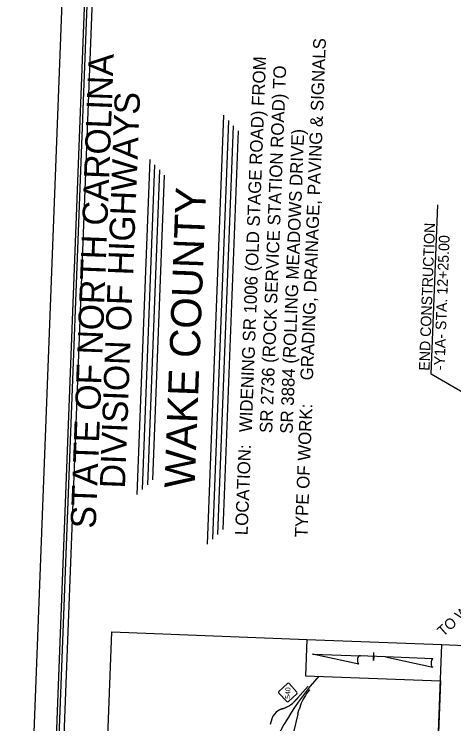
# Model space of a CAD drawing. Extents: x 2094564 to 2100382, y 679033 to 692366.
# Drawn here: x 2094564 to 2096747, y 684877 to 688399 of the extents above; entities that cross this region are included whole.
import ezdxf

# ---------------------------------------------------------------- set-up
doc = ezdxf.new("R2010")
doc.units = 0
for name, color, linetype in [('Old_Level_1', 7, 'Continuous'), ('Pattern 17', 7, 'Continuous'), ('Prop Horizontal Alignment Direction Label', 7, 'Continuous'), ('Prop Horizontal Alignment Station Label', 7, 'Continuous'), ('Prop Horizontal Alignment Tick Label', 7, 'Continuous'), ('Prop Horizontal Alignment Tick Large', 7, 'Continuous'), ('Scratch_Level_0', 7, 'Continuous')]:
    doc.layers.add(name, color=color, linetype=linetype)

msp = doc.modelspace()

# ---------------------------------------------------------------- linework, layer by layer
at = {"layer": 'Old_Level_1'}
for p, q in [((2096044.5, 685222.5), (2096044.5, 685222.3)), ((2096044.5, 685222.5), (2096044.5, 685222.3)), ((2096044.5, 685222.5), (2096283.3, 685213.4)), ((2096274.5, 685172.4), (2096044.5, 685222.3)), ((2096348.5, 685191.1), (2096350, 685231.1)), ((2096407.2, 685208.6), (2096276.3, 685213.7)), ((2096283.3, 685213.4), (2096276.6, 685213.6)), ((2096349.2, 685208.6), (2096348.5, 685190.9)), ((2096348.5, 685190.9), (2096348.5, 685190.6)), ((2096407.2, 685208.6), (2096641.7, 685157.9)), ((2096642.3, 685199.9), (2096407.2, 685208.6))]:
    msp.add_line(p, q, dxfattribs=at)
for centre, start_param, end_param in [((2096277.7, 685193), 0.216388, 2.908219), ((2096643.3, 685179), 0.201328, 3.141593)]:
    msp.add_ellipse(centre, major_axis=(1, 21.1), ratio=0.461098, start_param=start_param, end_param=end_param, dxfattribs=at)
at = {"layer": 'Pattern 17'}
for p, q in [((2096016.8, 685295.7), (2096687.2, 685270)), ((2095878.4, 685037.6), (2095920.5, 685076.5)), ((2095928.6, 685076.2), (2095967.6, 685034.2)), ((2095917, 684987.4), (2095878.1, 685029.4)), ((2095967.3, 685026), (2095925.2, 684987.1))]:
    msp.add_line(p, q, dxfattribs=at)
for points in [[(2094975.9, 683430.3), (2095048.9, 685332.8), (2096016.8, 685295.7), (2096009.9, 685115.7), (2096680.3, 685090), (2096614.3, 683367.4)], [(2096614.3, 683367.4), (2096687.2, 685270), (2096881.4, 685262.6), (2096808.4, 683360)]]:
    msp.add_lwpolyline(points, close=True, dxfattribs=at)
for centre, start, end in [((2095924.4, 685072.3), 42.8037, 132.8037), ((2095882.3, 685033.4), 132.8037, 222.8037), ((2095963.3, 685030.3), 312.8037, 42.8037), ((2095921.3, 684991.3), 222.8037, 312.8037)]:
    msp.add_arc(centre, 5.78, start, end, dxfattribs=at)
at = {"layer": 'Prop Horizontal Alignment Direction Label'}
for p, q in [((2095523.6, 685768.8), (2095605.3, 687897.3)), ((2095549.5, 685792.8), (2095629.3, 687871.3)), ((2095575.5, 685816.9), (2095653.3, 687845.4)), ((2095601.4, 685840.9), (2095677.4, 687819.4)), ((2095174.9, 686015.6), (2095238.6, 687678.1)), ((2095200.7, 686039.6), (2095262.6, 687652.2)), ((2095226.7, 686063.7), (2095286.6, 687626.3)), ((2095252.7, 686087.7), (2095310.6, 687600.3)), ((2096023.6, 685063.4), (2095970.3, 685003.4)), ((2095843.3, 684901.7), (2095834.1, 684873.9)), ((2095972.4, 684924.8), (2095951.4, 684835.4))]:
    msp.add_line(p, q, dxfattribs=at)
for points in [[(2095006.3, 690563.5), (2094722.6, 683168.8)], [(2095030.3, 690537.5), (2094758.2, 683442.8)]]:
    msp.add_lwpolyline(points, dxfattribs=at)
for centre, radius, start, end in [((2097122.1, 684172.2), 1406.2, 138.0034, 159.4705), ((2096223.9, 684878), 255.5, 144.4694, 164.2013), ((2095856.4, 685087.2), 140.6, 296.8602, 313.1346), ((2095913.2, 684878.8), 73.6, 120.2754, 161.8296)]:
    msp.add_arc(centre, radius, start, end, dxfattribs=at)
for points in [[(2096030.2, 685045.1), (2096030, 685044.8), (2096029.8, 685044.6), (2096029.6, 685044.3), (2096029.4, 685044.1), (2096029.2, 685043.8), (2096029, 685043.6), (2096028.8, 685043.3), (2096028.6, 685043.1), (2096028.4, 685042.8), (2096028.2, 685042.6), (2096028, 685042.3), (2096027.8, 685042.1), (2096027.6, 685041.8), (2096027.4, 685041.6), (2096027.2, 685041.3), (2096027.1, 685041.1), (2096026.9, 685040.8), (2096026.7, 685040.6), (2096026.5, 685040.3), (2096026.3, 685040.1), (2096026.1, 685039.8), (2096025.9, 685039.6), (2096025.7, 685039.3), (2096025.5, 685039.1), (2096025.3, 685038.8), (2096025.1, 685038.6), (2096024.9, 685038.3), (2096024.7, 685038.1), (2096024.5, 685037.9), (2096024.3, 685037.6), (2096024.1, 685037.4), (2096023.9, 685037.1), (2096023.7, 685036.9), (2096023.5, 685036.6), (2096023.3, 685036.3), (2096023.1, 685036.1), (2096023, 685035.8), (2096022.8, 685035.6), (2096022.6, 685035.3), (2096022.4, 685035.1), (2096022.2, 685034.8), (2096022, 685034.6), (2096021.8, 685034.3), (2096021.6, 685034.1), (2096021.4, 685033.8), (2096021.2, 685033.6), (2096021, 685033.3), (2096020.8, 685033.1), (2096020.7, 685032.8), (2096020.5, 685032.6), (2096020.3, 685032.3), (2096020.1, 685032.1), (2096019.9, 685031.8), (2096019.7, 685031.6), (2096019.5, 685031.3), (2096019.3, 685031.1), (2096019.1, 685030.8), (2096018.9, 685030.5), (2096018.8, 685030.3), (2096018.6, 685030), (2096018.4, 685029.8), (2096018.2, 685029.5), (2096018, 685029.3), (2096017.8, 685029), (2096017.6, 685028.8), (2096017.4, 685028.5), (2096017.3, 685028.2), (2096017.1, 685028), (2096016.9, 685027.7), (2096016.7, 685027.5), (2096016.5, 685027.2), (2096016.3, 685027), (2096016.1, 685026.7), (2096016, 685026.4)], [(2095970.3, 685003.4), (2095970, 685003.1), (2095969.8, 685002.8), (2095969.6, 685002.6), (2095969.4, 685002.3), (2095969.1, 685002.1), (2095968.9, 685001.8), (2095968.7, 685001.5), (2095968.4, 685001.3), (2095968.2, 685001), (2095968, 685000.8), (2095967.7, 685000.5), (2095967.5, 685000.2), (2095967.3, 685000), (2095967, 684999.7), (2095966.8, 684999.5), (2095966.6, 684999.2), (2095966.3, 684998.9), (2095966.1, 684998.7), (2095965.9, 684998.4), (2095965.6, 684998.2), (2095965.4, 684997.9), (2095965.2, 684997.6), (2095964.9, 684997.4), (2095964.7, 684997.1), (2095964.5, 684996.9), (2095964.2, 684996.6), (2095964, 684996.3), (2095963.8, 684996.1), (2095963.5, 684995.8), (2095963.3, 684995.6), (2095963.1, 684995.3), (2095962.8, 684995.1), (2095962.6, 684994.8), (2095962.4, 684994.5), (2095962.1, 684994.3), (2095961.9, 684994), (2095961.6, 684993.8), (2095961.4, 684993.5), (2095961.2, 684993.3), (2095960.9, 684993), (2095960.7, 684992.8), (2095960.5, 684992.5), (2095960.2, 684992.3), (2095960, 684992), (2095959.7, 684991.8), (2095959.5, 684991.5), (2095959.3, 684991.2), (2095959, 684991), (2095958.8, 684990.7), (2095958.5, 684990.5), (2095958.3, 684990.2), (2095958, 684990), (2095957.8, 684989.7), (2095957.6, 684989.5), (2095957.3, 684989.2), (2095957.1, 684989), (2095956.8, 684988.8), (2095956.6, 684988.5), (2095956.3, 684988.3), (2095956.1, 684988), (2095955.8, 684987.8), (2095955.6, 684987.5), (2095955.3, 684987.3), (2095955.1, 684987), (2095954.8, 684986.8), (2095954.6, 684986.5), (2095954.3, 684986.3), (2095954.1, 684986.1), (2095953.8, 684985.8), (2095953.6, 684985.6), (2095953.3, 684985.3), (2095953.1, 684985.1), (2095952.8, 684984.9), (2095952.6, 684984.6)], [(2095896.3, 684951.6), (2095896, 684951.5), (2095895.8, 684951.3), (2095895.5, 684951.2), (2095895.2, 684951.1), (2095894.9, 684951), (2095894.6, 684950.9), (2095894.4, 684950.8), (2095894.1, 684950.7), (2095893.8, 684950.6), (2095893.5, 684950.5), (2095893.2, 684950.3), (2095893, 684950.2), (2095892.7, 684950.1), (2095892.4, 684950), (2095892.1, 684949.9), (2095891.8, 684949.8), (2095891.6, 684949.7), (2095891.3, 684949.6), (2095891, 684949.4), (2095890.7, 684949.3), (2095890.4, 684949.2), (2095890.2, 684949.1), (2095889.9, 684949), (2095889.6, 684948.9), (2095889.3, 684948.8), (2095889.1, 684948.6), (2095888.8, 684948.5), (2095888.5, 684948.4), (2095888.2, 684948.3), (2095887.9, 684948.2), (2095887.7, 684948.1), (2095887.4, 684947.9), (2095887.1, 684947.8), (2095886.8, 684947.7), (2095886.6, 684947.6), (2095886.3, 684947.5), (2095886, 684947.3), (2095885.7, 684947.2), (2095885.5, 684947.1), (2095885.2, 684947), (2095884.9, 684946.8), (2095884.6, 684946.7), (2095884.4, 684946.6), (2095884.1, 684946.5), (2095883.8, 684946.3), (2095883.5, 684946.2), (2095883.3, 684946.1), (2095883, 684946), (2095882.7, 684945.8), (2095882.5, 684945.7), (2095882.2, 684945.6), (2095881.9, 684945.4), (2095881.6, 684945.3), (2095881.4, 684945.2), (2095881.1, 684945), (2095880.8, 684944.9), (2095880.6, 684944.8), (2095880.3, 684944.6), (2095880, 684944.5), (2095879.8, 684944.4), (2095879.5, 684944.2), (2095879.2, 684944.1), (2095879, 684944), (2095878.7, 684943.8), (2095878.4, 684943.7), (2095878.2, 684943.5), (2095877.9, 684943.4), (2095877.6, 684943.2), (2095877.4, 684943.1), (2095877.1, 684942.9), (2095876.9, 684942.8), (2095876.6, 684942.6), (2095876.3, 684942.5), (2095876.1, 684942.3)], [(2095896.3, 684951.6), (2095896.6, 684951.7), (2095897, 684951.8), (2095897.3, 684952), (2095897.6, 684952.1), (2095897.9, 684952.2), (2095898.3, 684952.3), (2095898.6, 684952.5), (2095898.9, 684952.6), (2095899.2, 684952.7), (2095899.6, 684952.9), (2095899.9, 684953), (2095900.2, 684953.1), (2095900.5, 684953.2), (2095900.8, 684953.4), (2095901.2, 684953.5), (2095901.5, 684953.6), (2095901.8, 684953.8), (2095902.1, 684953.9), (2095902.5, 684954), (2095902.8, 684954.1), (2095903.1, 684954.3), (2095903.4, 684954.4), (2095903.8, 684954.5), (2095904.1, 684954.7), (2095904.4, 684954.8), (2095904.7, 684954.9), (2095905, 684955.1), (2095905.4, 684955.2), (2095905.7, 684955.3), (2095906, 684955.5), (2095906.3, 684955.6), (2095906.7, 684955.7), (2095907, 684955.9), (2095907.3, 684956), (2095907.6, 684956.1), (2095907.9, 684956.3), (2095908.3, 684956.4), (2095908.6, 684956.5), (2095908.9, 684956.7), (2095909.2, 684956.8), (2095909.5, 684957), (2095909.9, 684957.1), (2095910.2, 684957.2), (2095910.5, 684957.4), (2095910.8, 684957.5), (2095911.1, 684957.6), (2095911.5, 684957.8), (2095911.8, 684957.9), (2095912.1, 684958.1), (2095912.4, 684958.2), (2095912.7, 684958.3), (2095913.1, 684958.5), (2095913.4, 684958.6), (2095913.7, 684958.8), (2095914, 684958.9), (2095914.3, 684959.1), (2095914.6, 684959.2), (2095915, 684959.4), (2095915.3, 684959.5), (2095915.6, 684959.7), (2095915.9, 684959.8), (2095916.2, 684959.9), (2095916.5, 684960.1), (2095916.8, 684960.2), (2095917.2, 684960.4), (2095917.5, 684960.6), (2095917.8, 684960.7), (2095918.1, 684960.9), (2095918.4, 684961), (2095918.7, 684961.2), (2095919, 684961.3), (2095919.4, 684961.5), (2095919.7, 684961.6), (2095920, 684961.8)], [(2095972.4, 684924.8), (2095972.4, 684925.1), (2095972.5, 684925.4), (2095972.6, 684925.7), (2095972.6, 684926), (2095972.7, 684926.3), (2095972.8, 684926.7), (2095972.9, 684927), (2095972.9, 684927.3), (2095973, 684927.6), (2095973.1, 684927.9), (2095973.1, 684928.2), (2095973.2, 684928.5), (2095973.3, 684928.8), (2095973.4, 684929.1), (2095973.4, 684929.4), (2095973.5, 684929.7), (2095973.6, 684930), (2095973.7, 684930.4), (2095973.7, 684930.7), (2095973.8, 684931), (2095973.9, 684931.3), (2095974, 684931.6), (2095974, 684931.9), (2095974.1, 684932.2), (2095974.2, 684932.5), (2095974.2, 684932.8), (2095974.3, 684933.1), (2095974.4, 684933.4), (2095974.5, 684933.7), (2095974.5, 684934.1), (2095974.6, 684934.4), (2095974.7, 684934.7), (2095974.8, 684935), (2095974.8, 684935.3), (2095974.9, 684935.6), (2095975, 684935.9), (2095975.1, 684936.2), (2095975.1, 684936.5), (2095975.2, 684936.8), (2095975.3, 684937.1), (2095975.4, 684937.4), (2095975.4, 684937.7), (2095975.5, 684938), (2095975.6, 684938.4), (2095975.7, 684938.7), (2095975.8, 684939), (2095975.8, 684939.3), (2095975.9, 684939.6), (2095976, 684939.9), (2095976.1, 684940.2), (2095976.1, 684940.5), (2095976.2, 684940.8), (2095976.3, 684941.1), (2095976.4, 684941.4), (2095976.5, 684941.7), (2095976.5, 684942), (2095976.6, 684942.3), (2095976.7, 684942.7), (2095976.8, 684943), (2095976.9, 684943.3), (2095977, 684943.6), (2095977, 684943.9), (2095977.1, 684944.2), (2095977.2, 684944.5), (2095977.3, 684944.8), (2095977.4, 684945.1), (2095977.4, 684945.4), (2095977.5, 684945.7), (2095977.6, 684946), (2095977.7, 684946.3), (2095977.8, 684946.6), (2095977.9, 684946.9), (2095978, 684947.2), (2095978, 684947.5)]]:
    msp.add_spline(points, degree=3, dxfattribs=at)
at = {"layer": 'Prop Horizontal Alignment Station Label'}
msp.add_line((2095490.3, 686843.6), (2095490.3, 686843.6), dxfattribs=at)
at = {"layer": 'Prop Horizontal Alignment Tick Label'}
msp.add_lwpolyline([(2099950.1, 682147.8), (2100269.5, 690474.2), (2094997.8, 690676.3), (2094678.5, 682349.9)], close=True, dxfattribs=at)
at = {"layer": 'Prop Horizontal Alignment Tick Large'}
msp.add_lwpolyline([(2094886.5, 690703.1), (2094563.9, 682289.3), (2100059.8, 682078.5), (2100382.4, 690492.3)], close=True, dxfattribs=at)
at = {"layer": 'Scratch_Level_0'}
for p, q in [((2096634.8, 686612.2), (2096667, 687452.3)), ((2097643.4, 686021.5), (2096634.8, 686612.2))]:
    msp.add_line(p, q, dxfattribs=at)

# ---------------------------------------------------------------- texts
at = {"layer": 'Pattern 17'}
msp.add_text('540', height=24.79, rotation=87.8037, dxfattribs=at).set_placement((2095933.5, 685000.2))
at = {"layer": 'Prop Horizontal Alignment Direction Label'}
for s, height, p in [('STATE OF NORTH CAROLINA', 124.999, (2094968.4, 685844.4)), ('DIVISION OF HIGHWAYS', 124.999, (2095113.6, 686043.5)), ('TYPE OF WORK:', 62.5, (2096019.3, 685800.8)), ('LOCATION: ', 62.5, (2095722.7, 685812.2))]:
    msp.add_text(s, height=height, rotation=87.8037, dxfattribs=at).set_placement(p)
at = {"layer": 'Scratch_Level_0'}
for s, height, rotation, p in [('GRADING, DRAINAGE, PAVING & SIGNALS', 62.5, 87.8037, (2096046.8, 686580.7)), ('WIDENING SR 1006 (OLD STAGE ROAD) FROM ', 62.5, 87.8037, (2095743.2, 686323.2)), ('SR 2736 (ROCK SERVICE STATION ROAD) TO ', 62.5, 87.8037, (2095844.7, 686319.3)), ('SR 3884 (ROLLING MEADOWS DRIVE)', 62.5, 87.8037, (2095946.2, 686315.4)), ('WAKE COUNTY', 150, 87.8037, (2095459.6, 686044.5)), ('END CONSTRUCTION', 52.591, 87.8037, (2096625.7, 686628.8)), ('-Y1A- STA. 12+25.00', 52.591, 87.8037, (2096700.3, 686631.2)), ('TO WILLOW', 52.56, 41.9482, (2096693.8, 685306.9))]:
    msp.add_text(s, height=height, rotation=rotation, dxfattribs=at).set_placement(p)

doc.saveas('drawing.dxf')
